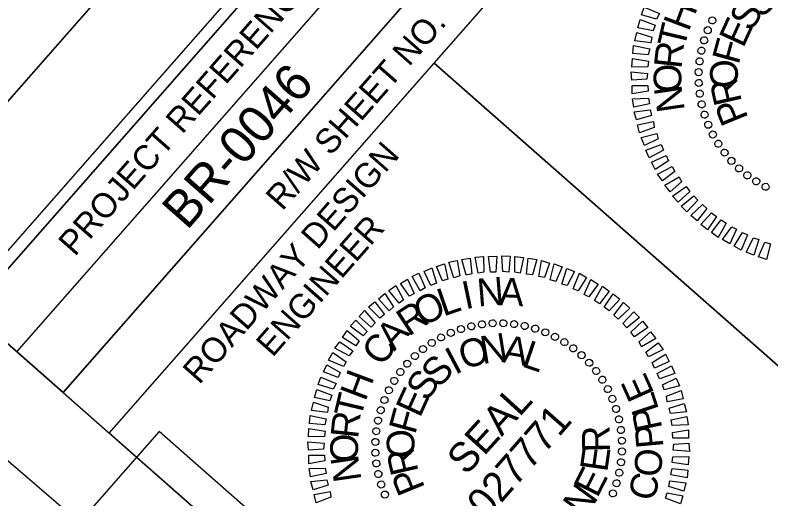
# Model space of a CAD drawing. Extents: x 2189835 to 2191772, y 387461 to 389531.
# Drawn here: x 2190828.7 to 2190982.4, y 389232.4 to 389330.6 of the extents above; entities that cross this region are included whole.
import ezdxf

# ---------------------------------------------------------------- set-up
doc = ezdxf.new("R2010")
doc.units = 0
for name, color, linetype in [('Sheet Clip Boundary CELL', 7, 'Continuous'), ('Sheet Cutting Line CELL', 7, 'Continuous'), ('Sheet Data Field CELL', 7, 'Continuous'), ('Sheet Layout Plan Border', 7, 'Continuous'), ('Sheet Plan CELL', 7, 'Continuous'), ('Sheet Plan Layout CELL', 7, 'Continuous'), ('Sheet Plot Border Inside CELL', 7, 'Continuous'), ('Sheet Plot Border Outside CELL', 7, 'Continuous'), ('Sheet Professional Seal CELL', 7, 'Continuous'), ('Sheet Sticker Exception Certification CELL', 7, 'Continuous')]:
    doc.layers.add(name, color=color, linetype=linetype)

msp = doc.modelspace()

# ---------------------------------------------------------------- linework, layer by layer
at = {"layer": 'Sheet Clip Boundary CELL'}
msp.add_lwpolyline([(2190233.88, 388250.3), (2190718.45, 387881.26), (2190850.4, 387777.99), (2191678.63, 388725.5), (2191058.62, 389246.4), (2190957.74, 389128.02), (2190818.15, 389247.91), (2190051.03, 388378.47)], close=True, dxfattribs=at)
at = {"layer": 'Sheet Cutting Line CELL'}
msp.add_line((2190946.11, 389448.37), (2189834.54, 388184.02), dxfattribs=at)
at = {"layer": 'Sheet Layout Plan Border'}
msp.add_lwpolyline([(2190847.19, 387643.49), (2191771.58, 388694.94), (2191141.84, 389248.59), (2191016.87, 389106.45), (2190858.04, 389246.09), (2190058.62, 388336.78)], close=True, dxfattribs=at)
at = {"layer": 'Sheet Plan CELL'}
for p, q in [((2190829.09, 389262.23), (2190961.19, 389412.46)), ((2190838.52, 389253.96), (2190970.58, 389404.21)), ((2190838.52, 389253.96), (2190970.58, 389404.21)), ((2190913.95, 389320.85), (2190998.42, 389246.61)), ((2190838.52, 389253.96), (2190847.89, 389245.71))]:
    msp.add_line(p, q, dxfattribs=at)
for points in [[(2190951.79, 389420.78), (2189961.36, 388294.21), (2190749.93, 387600.92), (2191740.35, 388727.47)], [(2190819.67, 389270.52), (2190951.79, 389420.78), (2190970.58, 389404.21), (2190838.52, 389253.96)], [(2190913.95, 389320.85), (2190979.96, 389395.96), (2191064.47, 389321.68), (2190998.45, 389246.57)], [(2190749.93, 387600.92), (2189961.36, 388294.17), (2190819.67, 389270.52), (2190932.38, 389171.45), (2191064.47, 389321.68), (2191740.35, 388727.47)], [(2190847.89, 389245.71), (2190913.95, 389320.85), (2190998.45, 389246.57), (2190932.38, 389171.45)]]:
    msp.add_lwpolyline(points, close=True, dxfattribs=at)
at = {"layer": 'Sheet Plan Layout CELL'}
msp.add_lwpolyline([(2190952.63, 389101.43), (2191110.61, 389281.13), (2190951.8, 389420.79), (2190793.79, 389241.07)], close=True, dxfattribs=at)
at = {"layer": 'Sheet Plot Border Inside CELL'}
msp.add_lwpolyline([(2190650.48, 387483.99), (2191750.47, 388735.2), (2190958.16, 389431.79), (2189858.14, 388180.58)], close=True, dxfattribs=at)
at = {"layer": 'Sheet Plot Border Outside CELL'}
msp.add_lwpolyline([(2190656.91, 387461.02), (2191768.48, 388725.38), (2190946.11, 389448.37), (2189834.54, 388184.02)], close=True, dxfattribs=at)
at = {"layer": 'Sheet Professional Seal CELL'}
for p, q in [((2190970.42, 389329.52), (2190970.42, 389329.52)), ((2190969.49, 389327.54), (2190969.49, 389327.54)), ((2190968.77, 389325.51), (2190968.77, 389325.51)), ((2190968.24, 389323.38), (2190968.24, 389323.38)), ((2190967.85, 389321.2), (2190967.85, 389321.2)), ((2190967.64, 389319.06), (2190967.64, 389319.06)), ((2190967.68, 389316.83), (2190967.68, 389316.83)), ((2190967.86, 389314.68), (2190967.86, 389314.68)), ((2190968.29, 389312.51), (2190968.29, 389312.51)), ((2190968.82, 389310.38), (2190968.82, 389310.38)), ((2190969.63, 389308.35), (2190969.63, 389308.35)), ((2190970.54, 389306.35), (2190970.54, 389306.35)), ((2190971.66, 389304.44), (2190971.66, 389304.44)), ((2190972.94, 389302.72), (2190972.94, 389302.72)), ((2190974.33, 389301.04), (2190974.33, 389301.04)), ((2190975.89, 389299.48), (2190975.89, 389299.48)), ((2190977.57, 389298.07), (2190977.57, 389298.07)), ((2190979.39, 389296.88), (2190979.39, 389296.88)), ((2190981.31, 389295.73), (2190981.31, 389295.73)), ((2190921.47, 389267.46), (2190921.47, 389267.46)), ((2190923.64, 389267.88), (2190923.64, 389267.88)), ((2190925.79, 389268.06), (2190925.79, 389268.06)), ((2190928.02, 389268.1), (2190928.02, 389268.1)), ((2190930.16, 389267.89), (2190930.16, 389267.89)), ((2190932.35, 389267.51), (2190932.35, 389267.51)), ((2190917.31, 389266.12), (2190917.31, 389266.12)), ((2190919.35, 389266.93), (2190919.35, 389266.93)), ((2190934.47, 389266.97), (2190934.47, 389266.97)), ((2190936.5, 389266.26), (2190936.5, 389266.26)), ((2190913.4, 389264.09), (2190913.4, 389264.09)), ((2190915.31, 389265.2), (2190915.31, 389265.2)), ((2190938.48, 389265.33), (2190938.48, 389265.33)), ((2190940.4, 389264.18), (2190940.4, 389264.18)), ((2190911.68, 389262.8), (2190911.68, 389262.8)), ((2190942.21, 389262.99), (2190942.21, 389262.99)), ((2190910, 389261.41), (2190910, 389261.41)), ((2190943.9, 389261.58), (2190943.9, 389261.58)), ((2190908.44, 389259.86), (2190908.44, 389259.86)), ((2190945.46, 389260.01), (2190945.46, 389260.01)), ((2190907.03, 389258.17), (2190907.03, 389258.17)), ((2190946.85, 389258.34), (2190946.85, 389258.34)), ((2190905.84, 389256.35), (2190905.84, 389256.35)), ((2190948.13, 389256.61), (2190948.13, 389256.61)), ((2190904.69, 389254.44), (2190904.69, 389254.44)), ((2190949.25, 389254.7), (2190949.25, 389254.7)), ((2190903.76, 389252.46), (2190903.76, 389252.46)), ((2190950.16, 389252.71), (2190950.16, 389252.71)), ((2190903.04, 389250.43), (2190903.04, 389250.43)), ((2190950.97, 389250.67), (2190950.97, 389250.67)), ((2190902.51, 389248.3), (2190902.51, 389248.3)), ((2190951.5, 389248.55), (2190951.5, 389248.55)), ((2190902.13, 389246.12), (2190902.13, 389246.12)), ((2190951.93, 389246.38), (2190951.93, 389246.38)), ((2190952.11, 389244.23), (2190952.11, 389244.23)), ((2190901.91, 389243.98), (2190901.91, 389243.98)), ((2190927.03, 389242.99), (2190927.03, 389242.99)), ((2190901.96, 389241.75), (2190901.96, 389241.75)), ((2190952.15, 389242), (2190952.15, 389242)), ((2190902.13, 389239.6), (2190902.13, 389239.6)), ((2190951.94, 389239.86), (2190951.94, 389239.86)), ((2190902.56, 389237.43), (2190902.56, 389237.43)), ((2190951.55, 389237.67), (2190951.55, 389237.67)), ((2190903.09, 389235.3), (2190903.09, 389235.3)), ((2190951.02, 389235.55), (2190951.02, 389235.55)), ((2190903.9, 389233.27), (2190903.9, 389233.27)), ((2190950.3, 389233.51), (2190950.3, 389233.51))]:
    msp.add_line(p, q, dxfattribs=at)
for points in [[(2190959.13, 389329.76), (2190956.09, 389330.69), (2190956.63, 389332.22), (2190959.73, 389330.9)], [(2190958.47, 389327.41), (2190955.31, 389328.05), (2190955.81, 389329.68), (2190958.86, 389328.54)], [(2190957.96, 389325), (2190954.71, 389325.39), (2190955.13, 389327.08), (2190958.14, 389326.11)], [(2190957.45, 389322.53), (2190954.31, 389322.81), (2190954.46, 389324.42), (2190957.73, 389323.75)], [(2190957.33, 389320.11), (2190954.11, 389320.07), (2190954.21, 389321.78), (2190957.47, 389321.25)], [(2190957.18, 389317.58), (2190954.07, 389317.38), (2190953.96, 389319.07), (2190957.28, 389318.76)], [(2190957.41, 389315.19), (2190954.19, 389314.62), (2190954.14, 389316.32), (2190957.33, 389316.32)], [(2190957.69, 389312.62), (2190954.51, 389311.95), (2190954.25, 389313.63), (2190957.47, 389313.74)], [(2190958.13, 389310.24), (2190955.07, 389309.33), (2190954.6, 389311), (2190957.84, 389311.36)], [(2190958.64, 389307.79), (2190955.67, 389306.68), (2190955.28, 389308.35), (2190958.49, 389308.99)], [(2190959.47, 389305.48), (2190956.65, 389304.15), (2190955.98, 389305.74), (2190959.15, 389306.55)], [(2190960.54, 389303.21), (2190957.64, 389301.63), (2190956.96, 389303.22), (2190960.04, 389304.31)], [(2190961.54, 389301.01), (2190958.82, 389299.27), (2190958.08, 389300.78), (2190961.11, 389302.11)], [(2190962.85, 389298.86), (2190960.32, 389296.96), (2190959.31, 389298.31), (2190962.32, 389299.85)], [(2190964.23, 389296.79), (2190961.89, 389294.72), (2190960.84, 389296.11), (2190963.7, 389297.78)], [(2190965.88, 389294.81), (2190963.55, 389292.6), (2190962.4, 389293.87), (2190965.15, 389295.79)], [(2190967.53, 389293.04), (2190965.31, 389290.66), (2190964.13, 389291.82), (2190966.69, 389293.91)], [(2190969.37, 389291.36), (2190967.35, 389288.81), (2190966.07, 389289.93), (2190968.47, 389292.15)], [(2190971.29, 389289.75), (2190969.45, 389287.04), (2190968.1, 389288.08), (2190970.32, 389290.46)], [(2190973.29, 389288.39), (2190971.68, 389285.49), (2190970.3, 389286.49), (2190972.26, 389289.03)], [(2190975.39, 389287.15), (2190974.03, 389284.16), (2190972.56, 389285.05), (2190974.41, 389287.62)], [(2190977.59, 389286.02), (2190976.35, 389282.86), (2190974.91, 389283.72), (2190976.57, 389286.45)], [(2190979.93, 389285.04), (2190978.9, 389281.89), (2190977.37, 389282.5), (2190978.81, 389285.36)], [(2190982.29, 389284.17), (2190981.47, 389280.96), (2190979.84, 389281.53), (2190981.13, 389284.52)], [(2190920.43, 389277.8), (2190919.58, 389281.01), (2190921.26, 389281.26), (2190921.58, 389278.06)], [(2190922.85, 389278.21), (2190922.24, 389281.47), (2190923.93, 389281.58), (2190924.04, 389278.43)], [(2190925.35, 389278.42), (2190925, 389281.58), (2190926.69, 389281.69), (2190926.45, 389278.45)], [(2190927.86, 389278.55), (2190927.68, 389281.76), (2190929.39, 389281.66), (2190929.07, 389278.41)], [(2190930.31, 389278.39), (2190930.35, 389281.62), (2190932.06, 389281.38), (2190931.42, 389278.22)], [(2190932.71, 389278.02), (2190933.03, 389281.26), (2190934.78, 389280.99), (2190933.92, 389277.89)], [(2190915.65, 389276.67), (2190914.4, 389279.57), (2190916.02, 389280.13), (2190916.73, 389276.99)], [(2190917.95, 389277.25), (2190916.92, 389280.48), (2190918.57, 389280.76), (2190919.13, 389277.68)], [(2190935.22, 389277.55), (2190935.75, 389280.81), (2190937.34, 389280.27), (2190936.33, 389277.37)], [(2190937.5, 389276.88), (2190938.31, 389280.09), (2190939.95, 389279.53), (2190938.66, 389276.54)], [(2190911.07, 389274.63), (2190909.46, 389277.57), (2190910.83, 389278.23), (2190912.09, 389275.27)], [(2190913.27, 389275.7), (2190911.87, 389278.58), (2190913.42, 389279.29), (2190914.41, 389276.16)], [(2190939.86, 389276.01), (2190940.89, 389279.16), (2190942.42, 389278.56), (2190940.98, 389275.7)], [(2190942.19, 389275.03), (2190943.44, 389278.2), (2190944.87, 389277.34), (2190943.21, 389274.61)], [(2190908.91, 389273.53), (2190907.08, 389276.14), (2190908.47, 389276.97), (2190909.87, 389274.09)], [(2190944.39, 389273.9), (2190945.75, 389276.9), (2190947.23, 389276.01), (2190945.38, 389273.44)], [(2190906.84, 389272.15), (2190904.73, 389274.67), (2190906.15, 389275.69), (2190907.72, 389272.78)], [(2190946.5, 389272.66), (2190948.11, 389275.57), (2190949.49, 389274.56), (2190947.53, 389272.02)], [(2190904.75, 389270.6), (2190902.64, 389273.04), (2190903.91, 389274.12), (2190905.65, 389271.4)], [(2190948.5, 389271.31), (2190950.34, 389274.02), (2190951.68, 389272.97), (2190949.47, 389270.59)], [(2190902.87, 389269.06), (2190900.56, 389271.35), (2190901.87, 389272.39), (2190903.81, 389269.83)], [(2190950.41, 389269.7), (2190952.44, 389272.24), (2190953.72, 389271.12), (2190951.32, 389268.91)], [(2190901.11, 389267.27), (2190898.66, 389269.41), (2190899.79, 389270.62), (2190901.94, 389268.14)], [(2190952.26, 389268.01), (2190954.48, 389270.39), (2190955.65, 389269.23), (2190953.1, 389267.15)], [(2190899.49, 389265.5), (2190896.88, 389267.45), (2190898.01, 389268.66), (2190900.32, 389266.37)], [(2190953.9, 389266.25), (2190956.24, 389268.46), (2190957.38, 389267.19), (2190954.64, 389265.27)], [(2190898.03, 389263.45), (2190895.26, 389265.15), (2190896.23, 389266.56), (2190898.71, 389264.46)], [(2190955.56, 389264.26), (2190957.9, 389266.33), (2190958.95, 389264.95), (2190956.08, 389263.27)], [(2190896.68, 389261.45), (2190893.74, 389262.96), (2190894.72, 389264.3), (2190897.36, 389262.45)], [(2190956.94, 389262.19), (2190959.47, 389264.1), (2190960.48, 389262.75), (2190957.46, 389261.2)], [(2190895.51, 389259.28), (2190892.45, 389260.57), (2190893.31, 389262.08), (2190896.01, 389260.24)], [(2190958.25, 389260.05), (2190960.97, 389261.79), (2190961.7, 389260.28), (2190958.68, 389258.94)], [(2190894.42, 389257.05), (2190891.4, 389258.16), (2190892.09, 389259.62), (2190894.85, 389258.07)], [(2190959.24, 389257.85), (2190962.15, 389259.42), (2190962.82, 389257.84), (2190959.74, 389256.75)], [(2190893.41, 389254.68), (2190890.37, 389255.61), (2190890.91, 389257.13), (2190894, 389255.82)], [(2190960.32, 389255.58), (2190963.13, 389256.9), (2190963.81, 389255.32), (2190960.64, 389254.5)], [(2190892.75, 389252.33), (2190889.59, 389252.97), (2190890.08, 389254.6), (2190893.13, 389253.46)], [(2190961.14, 389253.26), (2190964.12, 389254.38), (2190964.51, 389252.71), (2190961.29, 389252.07)], [(2190892.23, 389249.92), (2190888.98, 389250.31), (2190889.4, 389252), (2190892.41, 389251.03)], [(2190961.66, 389250.82), (2190964.72, 389251.73), (2190965.18, 389250.06), (2190961.95, 389249.7)], [(2190891.73, 389247.44), (2190888.59, 389247.73), (2190888.73, 389249.34), (2190892, 389248.67)], [(2190962.1, 389248.44), (2190965.28, 389249.11), (2190965.54, 389247.42), (2190962.32, 389247.32)], [(2190891.6, 389245.03), (2190888.38, 389244.99), (2190888.48, 389246.7), (2190891.74, 389246.17)], [(2190962.38, 389245.87), (2190965.6, 389246.44), (2190965.64, 389244.74), (2190962.45, 389244.74)], [(2190891.45, 389242.5), (2190888.35, 389242.29), (2190888.24, 389243.99), (2190891.55, 389243.68)], [(2190962.61, 389243.47), (2190965.71, 389243.68), (2190965.83, 389241.99), (2190962.51, 389242.3)], [(2190891.68, 389240.11), (2190888.46, 389239.54), (2190888.42, 389241.24), (2190891.61, 389241.24)], [(2190962.46, 389240.95), (2190965.68, 389240.98), (2190965.58, 389239.28), (2190962.32, 389239.8)], [(2190891.96, 389237.54), (2190888.78, 389236.87), (2190888.53, 389238.55), (2190891.74, 389238.66)], [(2190962.33, 389238.53), (2190965.47, 389238.24), (2190965.33, 389236.64), (2190962.06, 389237.31)], [(2190892.4, 389235.16), (2190889.34, 389234.25), (2190888.88, 389235.92), (2190892.11, 389236.27)], [(2190961.83, 389236.05), (2190965.08, 389235.66), (2190964.66, 389233.97), (2190961.65, 389234.94)], [(2190892.92, 389232.71), (2190889.94, 389231.59), (2190889.55, 389233.27), (2190892.77, 389233.91)], [(2190961.31, 389233.64), (2190964.47, 389233), (2190963.98, 389231.38), (2190960.93, 389232.52)]]:
    msp.add_lwpolyline(points, close=True, dxfattribs=at)
for centre, major_axis in [((2190970.45, 389329.53), (-0.64, 0.329)), ((2190969.54, 389327.54), (-0.667, 0.272)), ((2190968.8, 389325.48), (-0.688, 0.213)), ((2190968.24, 389323.37), (-0.704, 0.152)), ((2190967.87, 389321.21), (-0.714, 0.09)), ((2190967.69, 389319.03), (-0.719, 0.028)), ((2190967.71, 389316.84), (-0.719, -0.035)), ((2190967.91, 389314.66), (-0.713, -0.098)), ((2190968.3, 389312.51), (-0.702, -0.16)), ((2190968.88, 389310.4), (-0.686, -0.22)), ((2190969.64, 389308.35), (-0.664, -0.279)), ((2190970.57, 389306.37), (-0.637, -0.336)), ((2190971.68, 389304.48), (-0.605, -0.39)), ((2190972.94, 389302.7), (-0.569, -0.441)), ((2190974.35, 389301.03), (-0.528, -0.489)), ((2190975.91, 389299.49), (-0.484, -0.533)), ((2190977.59, 389298.09), (-0.435, -0.574)), ((2190979.39, 389296.85), (-0.384, -0.609)), ((2190981.29, 389295.76), (-0.329, -0.64)), ((2190923.63, 389267.83), (-0.098, 0.713)), ((2190925.8, 389268.04), (-0.035, 0.719)), ((2190927.99, 389268.05), (0.028, 0.719)), ((2190930.17, 389267.87), (0.09, 0.714)), ((2190919.36, 389266.87), (-0.22, 0.686)), ((2190921.47, 389267.44), (-0.16, 0.702)), ((2190932.33, 389267.5), (0.152, 0.704)), ((2190934.45, 389266.95), (0.213, 0.688)), ((2190936.51, 389266.21), (0.272, 0.667)), ((2190915.33, 389265.17), (-0.336, 0.637)), ((2190917.31, 389266.11), (-0.279, 0.664)), ((2190938.49, 389265.29), (0.329, 0.64)), ((2190913.44, 389264.07), (-0.39, 0.605)), ((2190940.39, 389264.21), (0.384, 0.609)), ((2190911.66, 389262.8), (-0.441, 0.569)), ((2190942.19, 389262.96), (0.435, 0.574)), ((2190909.99, 389261.39), (-0.489, 0.528)), ((2190943.88, 389261.57), (0.484, 0.533)), ((2190908.45, 389259.83), (-0.533, 0.484)), ((2190945.43, 389260.03), (0.528, 0.489)), ((2190907.05, 389258.15), (-0.574, 0.435)), ((2190946.85, 389258.36), (0.569, 0.441)), ((2190905.81, 389256.35), (-0.609, 0.384)), ((2190948.11, 389256.57), (0.605, 0.39)), ((2190904.72, 389254.45), (-0.64, 0.329)), ((2190949.22, 389254.68), (0.637, 0.336)), ((2190903.81, 389252.46), (-0.667, 0.272)), ((2190950.15, 389252.71), (0.664, 0.279)), ((2190903.07, 389250.4), (-0.688, 0.213)), ((2190950.91, 389250.65), (0.686, 0.22)), ((2190902.52, 389248.29), (-0.704, 0.152)), ((2190951.49, 389248.54), (0.702, 0.16)), ((2190951.88, 389246.39), (0.713, 0.098)), ((2190902.15, 389246.13), (-0.714, 0.09)), ((2190901.97, 389243.95), (-0.719, 0.028)), ((2190952.08, 389244.21), (0.719, 0.035)), ((2190901.98, 389241.76), (-0.719, -0.035)), ((2190952.09, 389242.02), (0.719, -0.028)), ((2190902.18, 389239.58), (-0.713, -0.098)), ((2190951.91, 389239.84), (0.714, -0.09)), ((2190902.57, 389237.43), (-0.702, -0.16)), ((2190951.54, 389237.69), (0.704, -0.152)), ((2190950.99, 389235.57), (0.688, -0.213)), ((2190903.15, 389235.32), (-0.686, -0.22)), ((2190903.91, 389233.27), (-0.664, -0.279)), ((2190950.25, 389233.51), (0.667, -0.272))]:
    msp.add_ellipse(centre, major_axis=major_axis, ratio=0.999708, dxfattribs=at)

# ---------------------------------------------------------------- texts
at = {"layer": 'Sheet Data Field CELL'}
msp.add_text('BR-0046', height=7.5, rotation=48.6794, dxfattribs=at).set_placement((2190863.67, 389286.76))
at = {"layer": 'Sheet Plan CELL'}
for s, height, p in [('PROJECT REFERENCE NO.', 5.0001, (2190840.88, 389281.44)), ('R/W SHEET NO.', 5.0001, (2190883.05, 389290.7)), ('ROADWAY DESIGN', 5.0001, (2190866.17, 389255.45)), ('ENGINEER', 5, (2190881.07, 389260.97))]:
    msp.add_text(s, height=height, rotation=48.6794, dxfattribs=at).set_placement(p)
at = {"layer": 'Sheet Professional Seal CELL'}
for s, height, rotation, p in [('S', 5.64, 46.7018, (2190980.57, 389329.8)), ('H', 5.64, 69.4209, (2190965.65, 389327.11)), ('S', 5.64, 56.057, (2190978.23, 389327.06)), ('E', 5.64, 65.4124, (2190976.75, 389323.77)), ('T', 5.64, 76.6212, (2190964.75, 389323.58)), ('F', 5.64, 74.7684, (2190975.77, 389320.38)), ('R', 5.64, 83.8219, (2190964.17, 389319.57)), ('O', 5.64, 93.4826, (2190975.82, 389315.95)), ('O', 5.64, 91.0231, (2190964.23, 389314.93)), ('R', 5.64, 102.841, (2190976.51, 389313.02)), ('N', 5.64, 98.2249, (2190964.9, 389311.29)), ('P', 5.64, 112.2003, (2190977.86, 389309.71)), ('I', 5.64, 11.8215, (2190920.25, 389270.85)), ('N', 5.64, 4.6203, (2190922.84, 389271.44)), ('A', 5.64, 357.4185, (2190927, 389271.72)), ('L', 5.64, 19.0223, (2190915.78, 389269.38)), ('O', 5.64, 26.2225, (2190911.49, 389267.29)), ('R', 5.64, 33.4225, (2190908.72, 389265.26)), ('A', 5.64, 47.8217, (2190905.8, 389262.23)), ('C', 5.64, 55.0213, (2190903.43, 389259.06)), ('N', 5.64, 9.278, (2190923.76, 389259.74)), ('O', 5.64, 18.6349, (2190920.04, 389258.54)), ('A', 5.64, 350.5616, (2190927.59, 389260.17)), ('L', 5.64, 341.2022, (2190931.47, 389259.37)), ('I', 5.64, 27.991, (2190918.2, 389257.49)), ('S', 5.64, 46.7018, (2190914.84, 389254.72)), ('H', 5.64, 69.4209, (2190899.93, 389252.03)), ('S', 5.64, 56.057, (2190912.51, 389251.98)), ('E', 5.5, 114.1472, (2190958.75, 389253.8)), ('E', 5.64, 65.4124, (2190911.03, 389248.69)), ('T', 5.64, 76.6212, (2190899.03, 389248.5)), ('SEAL', 5.998, 47.8014, (2190920.45, 389236.99)), ('L', 5.5, 108.337, (2190959.68, 389250.53)), ('F', 5.64, 74.7684, (2190910.05, 389245.3)), ('027771', 5.998, 48.8014, (2190924.56, 389228.01)), ('P', 5.5, 101.754, (2190960.33, 389246.74)), ('R', 5.64, 83.8219, (2190898.44, 389244.49)), ('P', 5.5, 95.1711, (2190960.54, 389242.9)), ('O', 5.64, 93.4826, (2190910.09, 389240.87)), ('R', 5.64, 91.2828, (2190949.67, 389241.9)), ('O', 5.64, 91.0231, (2190898.5, 389239.85)), ('R', 5.64, 102.841, (2190910.78, 389237.94)), ('E', 5.64, 81.9255, (2190949.1, 389237.69)), ('N', 5.64, 98.2249, (2190899.17, 389236.21)), ('O', 5.5, 84.4666, (2190959.94, 389236.68)), ('E', 5.64, 63.2131, (2190947.08, 389232.41)), ('P', 5.64, 112.2003, (2190912.14, 389234.63)), ('C', 5.5, 75.5938, (2190958.57, 389231.68)), ('N', 5.64, 53.8578, (2190944.27, 389228.29))]:
    msp.add_text(s, height=height, rotation=rotation, dxfattribs=at).set_placement(p)
at = {"layer": 'Sheet Sticker Exception Certification CELL'}
for s, p in [('DOCUMENT NOT CONSIDERED FINAL', (2190954.07, 389180.45)), ('UNLESS ALL SIGNATURES COMPLETED', (2190957.33, 389170.83))]:
    msp.add_text(s, height=5.5, rotation=48.6794, dxfattribs=at).set_placement(p)

doc.saveas('drawing.dxf')
